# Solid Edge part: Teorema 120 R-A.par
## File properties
Title: TEOREMA 120/R A
Author: DESYS
Template: Iso Part.par
Last saved by: PIM_1
Revision: 67
Application: Solid Edge
Tipo di contenuto documento: 0
Accuracy: 0.99000000000
Document Number: 8031 120R/A
Revision: 0
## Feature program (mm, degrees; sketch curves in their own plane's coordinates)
sketch for "unnamed Protrusion 1" plane through (10.8674, 10.8674, 0) normal (0, 0, 1) x-axis (1, 0, 0)
  line (-610.8674, 219.1326) -> (589.1326, 219.1326)
  line (589.1326, 219.1326) -> (589.1326, -240.8674)
  line (589.1326, -240.8674) -> (-610.8674, -240.8674)
  line (-610.8674, -240.8674) -> (-610.8674, 219.1326)
  dimension (linear) = 610.8674
  dimension (linear) = 610.8674
  dimension (linear) = 589.1326
  dimension (linear) = 589.1326
extrude "unnamed Protrusion 1" add finite 140 along -normal
sketch for "ScavoEstrusione_1" plane through (0, 0, 0) normal (0, 0, 1) x-axis (1, 0, 0)
  line (0, 0) -> (0, 0)
  line (0, 0) -> (0, 0)
  line (-585, -100) -> (585, -100)
  line (585, -100) -> (585, 215)
  line (-585, 215) -> (585, 215)
  line (-585, 215) -> (-585, -100)
  dimension (linear) = 585
  dimension (linear) = 585
extrude "ScavoEstrusione_1" cut finite 80 along -normal
sketch for "ScavoEstrusione_7" plane through (0, 0, -140) normal (0, 0, -1) x-axis (1, 0, 0)
  line (-500, 110) -> (500, 110)
  line (500, 205) -> (500, 110)
  line (-500, 205) -> (500, 205)
  line (-500, 110) -> (-500, 205)
  dimension (linear) = 500
  dimension (linear) = 500
extrude "ScavoEstrusione_7" cut finite 120 along -normal
sketch for "ScavoEstrusione_8" plane through (0, 0, -140) normal (0, 0, -1) x-axis (1, 0, 0)
  line (-540, -170) -> (340, -170)
  line (-540, 10.1259) -> (-540, -170)
  line (-500, 60.0629) -> (-540, 10.1259)
  line (-500, 110) -> (-500, 60.0629)
  line (-500, 110) -> (500, 110)
  line (500, 110) -> (500, 60.0629)
  line (500, 60.0629) -> (540, 10.1259)
  line (540, 10.1259) -> (540, -170)
  dimension (linear) = 540
  dimension (linear) = 540
  dimension (linear) = 500
extrude "ScavoEstrusione_8" cut finite 40 along -normal
sketch for "v_3" #1 plane through (0, 0, -140) normal (0, 0, -1) x-axis (1, 0, 0)
  line (-540, 9.8811) -> (-540, 205)
  line (-500, 205) -> (-540, 205)
  line (-500, 60.0629) -> (-500, 205)
  line (-500, 60.0629) -> (-540, 9.8811)
  dimension (linear) = 540
  dimension (linear) = 500
  dimension (linear) = 500
  dimension (linear) = 500
sketch for "v_3" #2 plane through (0, 0, -140) normal (0, 0, -1) x-axis (1, 0, 0)
  line (540, 9.8811) -> (540, 205)
  line (500, 205) -> (540, 205)
  line (500, 60.0629) -> (500, 205)
  line (500, 60.0629) -> (540, 9.8811)
extrude "v_3" cut finite 5 along -normal
sketch for "ScavoEstrusione_10" plane through (0, 0, 0) normal (0, 0, 1) x-axis (0, -1, 0)
  line (100, -585) -> (215, -585)
  line (215, -585) -> (215, 585)
  line (215, 585) -> (100, 585)
  line (100, 585) -> (100, -585)
extrude "ScavoEstrusione_10" cut finite 10 along -normal
sketch for "ScavoEstrusione_11" plane through (0, -157.5, -10) normal (0, 0, 1) x-axis (-1, 0, 0)
  circle centre (0, 0) radius 20
extrude "ScavoEstrusione_11" cut finite 665 along -normal
sketch for "unnamed Cutout 1" plane through (0, -100, -45) normal (0, 1, 0) x-axis (-1, 0, 0)
  circle centre (0, 2.5) radius 12.5
extrude "unnamed Cutout 1" cut to key point along -normal
sketch for "ScavoEstrusione_14" #1 plane through (0, -230, -70) normal (0, -1, 0) x-axis (1, 0, 0)
  line (-310, 2.5) -> (-300, 2.5)
  arc centre (-300, -10) radius 12.5 from (-300, 2.5) to (-300, -22.5) cw
  line (-300, -22.5) -> (-310, -22.5)
  arc centre (-310, -10) radius 12.5 from (-310, -22.5) to (-310, 2.5) cw
sketch for "ScavoEstrusione_14" #2 plane through (0, -230, -70) normal (0, -1, 0) x-axis (1, 0, 0)
  line (300, 2.5) -> (310, 2.5)
  arc centre (310, -10) radius 12.5 from (310, 2.5) to (310, -22.5) cw
  line (310, -22.5) -> (300, -22.5)
  arc centre (300, -10) radius 12.5 from (300, -22.5) to (300, 2.5) cw
extrude "ScavoEstrusione_14" cut finite 35 along -normal
sketch for "ProtrusioneEstrusa_2" plane through (0, 30, -100) normal (0, 0, -1) x-axis (-1, 0, 0)
  circle centre (0, -15) radius 35
extrude "ProtrusioneEstrusa_2" add finite 30 along +normal
sketch for "ScavoEstrusione_15" plane through (-0.8459, 15.0679, -130) normal (0, 0, -1) x-axis (-1, 0, 0)
  circle centre (-0.8459, -0.0679) radius 30
extrude "ScavoEstrusione_15" cut finite 455 along -normal
sketch for "ScavoEstrusione_16" #1 plane through (-500, -132.5315, -77.5) normal (1, 0, 0) x-axis (0, -1, 0)
  circle centre (40.3976, 16.9065) radius 7.5
sketch for "ScavoEstrusione_16" #2 plane through (-500, -132.5315, -77.5) normal (1, 0, 0) x-axis (0, -1, 0)
  circle centre (-753.2679, -1216.4618) radius 7.5
sketch for "ScavoEstrusione_16" #3 plane through (-500, -132.5315, -77.5) normal (1, 0, 0) x-axis (0, -1, 0)
  circle centre (40.3976, 16.9065) radius 7.5
extrude "ScavoEstrusione_16" cut finite 35 along -normal
draft "Spoglia_1"  Angles1 = 5 deg
draft "Spoglia_2"  Angles1 = 5 deg
draft "Spoglia_4"  Angles1 = 4 deg
draft "Spoglia_5"  Angles1 = 4 deg
draft "Spoglia_6"  Angles1 = 4 deg
draft "Spoglia_7"  Angles1 = 5 deg
draft "Spoglia_8"  Angles1 = 5 deg
sketch for "ProtrusioneEstrusa_4" plane through (0, 0, -70) normal (1, 0, 0) x-axis (0, -1, 0)
  line (20, 55) -> (130, 55)
  line (130, 55) -> (130, -50)
  line (130, -50) -> (110, -50)
  line (110, -50) -> (110, 30)
  line (51.3251, 30) -> (110, 30)
extrude "ProtrusioneEstrusa_4" add finite 50 symmetric
sketch for "unnamed Protrusion 2" plane through (-0.8459, -130, -72.5) normal (0, -1, 0) x-axis (-1, 0, 0)
  line (-25.8459, -7.5) -> (-85.8459, -52.5)
extrude "unnamed Protrusion 2" add through along -normal
fillet "Rotondo_4" radius 35
fillet "Rotondo_5" radius 40
fillet "Rotondo_6" radius 7
fillet "Rotondo_8" radius 5
fillet "Rotondo_10" radius 5
fillet "Rotondo_12" radius 3
fillet "Rotondo_14" radius 5
fillet "Rotondo_15" radius 10
fillet "Rotondo_16" radius 3
fillet "Rotondo_17" radius 7.5
fillet "Rotondo_18" radius 7.5
fillet "Rotondo_20" radius 7.5
fillet "Rotondo_21" radius 5
fillet "unnamed Round 1"
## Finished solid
Body 1: solid body, 179 faces, 399 edges, 222 vertices.
  Faces by surface: cylinder 85, plane 38, torus 33, blend 19, sphere 4
  Edges by curve: line 171, circle 160, ellipse 40, intersection 28
Bounding box of the edges (mm; curved faces can reach further): 1200.000 x 460.000 x 140.000, from (-600, -230, -140) to (600, 230, 0).
Cylindrical faces by radius (mm): R3 x12, R5 x34, R7 x4, R7.5 x14, R10 x4, R12.5 x5, R20 x1, R30 x1, R35 x6, R40 x4
Toroidal faces (ring radius, tube radius in mm): R2.5 r7.5 x8, R10 r5 x6, R12 r5 x1, R15.5 r3 x1, R17.5 r5 x8, R23 r3 x1, R28 r7 x2, R32 r2 x1, R33 r2 x1, R40 r10 x1, R42.5 r7.5 x1, R47.5 r7.5 x2
Spherical faces by radius (mm): R5 x4
Planar faces by outward normal: +x 4, +y 4, +z 5, -x 3, -y 5, -z 9, oblique 8
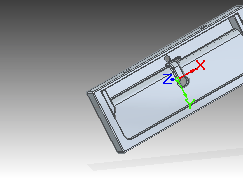
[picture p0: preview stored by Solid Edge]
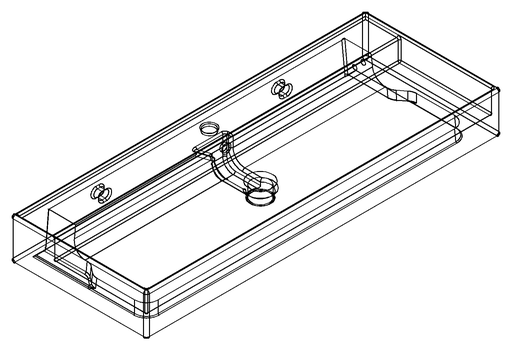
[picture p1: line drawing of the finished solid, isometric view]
